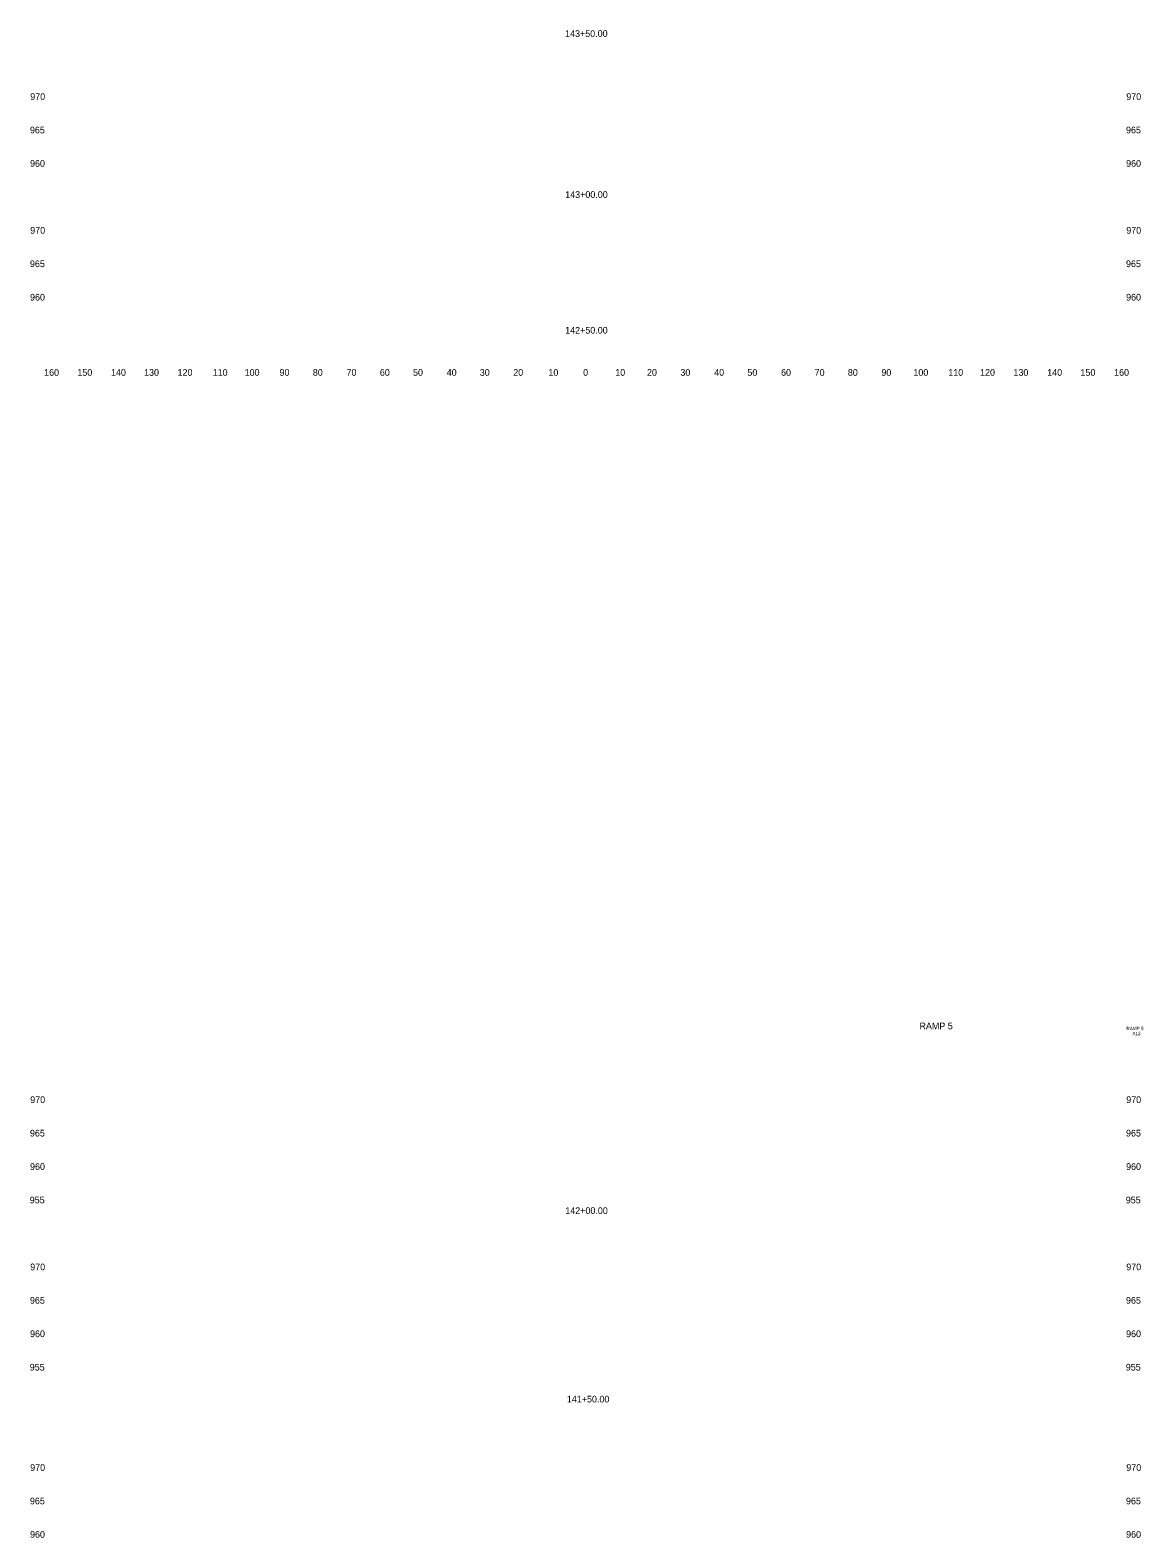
# Model space of a CAD drawing. Extents: x 4994 to 5842, y 4997 to 8804.
# Drawn here: x 5508.9 to 5841.7, y 5450 to 5900.9 of the extents above; entities that cross this region are included whole.
import ezdxf

# ---------------------------------------------------------------- set-up
doc = ezdxf.new("R2010")
doc.units = 0
for name, color, linetype in [('CLS_Search_Dist', 7, 'Continuous'), ('RD_XE_Ground', 7, 'Continuous'), ('UC_PD_Text', 7, 'Continuous')]:
    doc.layers.add(name, color=color, linetype=linetype)

msp = doc.modelspace()

# ---------------------------------------------------------------- texts
at = {"layer": 'CLS_Search_Dist'}
for s, p in [('970', (5508.94, 5880)), ('970', (5836.74, 5880)), ('965', (5508.86, 5870)), ('965', (5836.66, 5870)), ('960', (5508.89, 5860)), ('960', (5836.69, 5860)), ('970', (5508.94, 5840)), ('970', (5836.74, 5840)), ('965', (5508.86, 5830)), ('965', (5836.66, 5830)), ('960', (5508.89, 5820)), ('960', (5836.69, 5820)), ('160', (5513.1, 5797.5)), ('150', (5523.04, 5797.5)), ('140', (5533.1, 5797.5)), ('130', (5542.99, 5797.5)), ('120', (5553.01, 5797.5)), ('110', (5563.51, 5797.5)), ('100', (5573.07, 5797.5)), ('90', (5583.5, 5797.5)), ('80', (5593.46, 5797.5)), ('70', (5603.54, 5797.5)), ('60', (5613.5, 5797.5)), ('50', (5623.43, 5797.5)), ('40', (5633.5, 5797.5)), ('30', (5643.39, 5797.5)), ('20', (5653.4, 5797.5)), ('10', (5663.91, 5797.5)), ('0', (5674.3, 5797.5)), ('0', (5674.3, 5797.5)), ('10', (5683.91, 5797.5)), ('20', (5693.4, 5797.5)), ('30', (5703.39, 5797.5)), ('40', (5713.5, 5797.5)), ('50', (5723.43, 5797.5)), ('60', (5733.5, 5797.5)), ('70', (5743.54, 5797.5)), ('80', (5753.46, 5797.5)), ('90', (5763.5, 5797.5)), ('100', (5773.07, 5797.5)), ('110', (5783.51, 5797.5)), ('120', (5793.01, 5797.5)), ('130', (5802.99, 5797.5)), ('140', (5813.1, 5797.5)), ('150', (5823.04, 5797.5)), ('160', (5833.1, 5797.5)), ('970', (5508.94, 5580)), ('970', (5836.74, 5580)), ('965', (5508.86, 5570)), ('965', (5836.66, 5570)), ('960', (5508.89, 5560)), ('960', (5836.69, 5560)), ('955', (5508.8, 5550)), ('955', (5836.6, 5550)), ('970', (5508.94, 5530)), ('970', (5836.74, 5530)), ('965', (5508.86, 5520)), ('965', (5836.66, 5520)), ('960', (5508.89, 5510)), ('960', (5836.69, 5510)), ('955', (5508.8, 5500)), ('955', (5836.6, 5500)), ('970', (5508.94, 5470)), ('970', (5836.74, 5470)), ('965', (5508.86, 5460)), ('965', (5836.66, 5460)), ('960', (5508.89, 5450)), ('960', (5836.69, 5450))]:
    msp.add_text(s, height=2, dxfattribs=at).set_placement(p)
at = {"layer": 'RD_XE_Ground'}
for s, p in [('143+50.00', (5668.91, 5898.84)), ('143+00.00', (5668.94, 5850.69)), ('142+50.00', (5668.93, 5810.12)), ('142+00.00', (5668.96, 5546.83)), ('141+50.00', (5669.43, 5490.46))]:
    msp.add_text(s, height=2, dxfattribs=at).set_placement(p)
at = {"layer": 'UC_PD_Text'}
for s, height, p in [('RAMP 5', 2, (5774.89, 5602.06)), ('RAMP 5', 1, (5836.78, 5601.8)), ('X12', 1, (5838.57, 5600.3))]:
    msp.add_text(s, height=height, dxfattribs=at).set_placement(p)

doc.saveas('drawing.dxf')
